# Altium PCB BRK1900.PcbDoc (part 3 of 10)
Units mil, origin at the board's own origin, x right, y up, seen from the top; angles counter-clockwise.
Board outline 8858.27 x 5905.51 mil, 10 copper layers (L1-TOP, L2-GND, L3-SIG1, L4-GND, L5-PWR, L6-PWR, L7-GND, L8-SIG2, L9-GND, L10-BOT), stack 48.824 mil thick; 507 components, 607 nets, 2498 pads, 2210 vias.
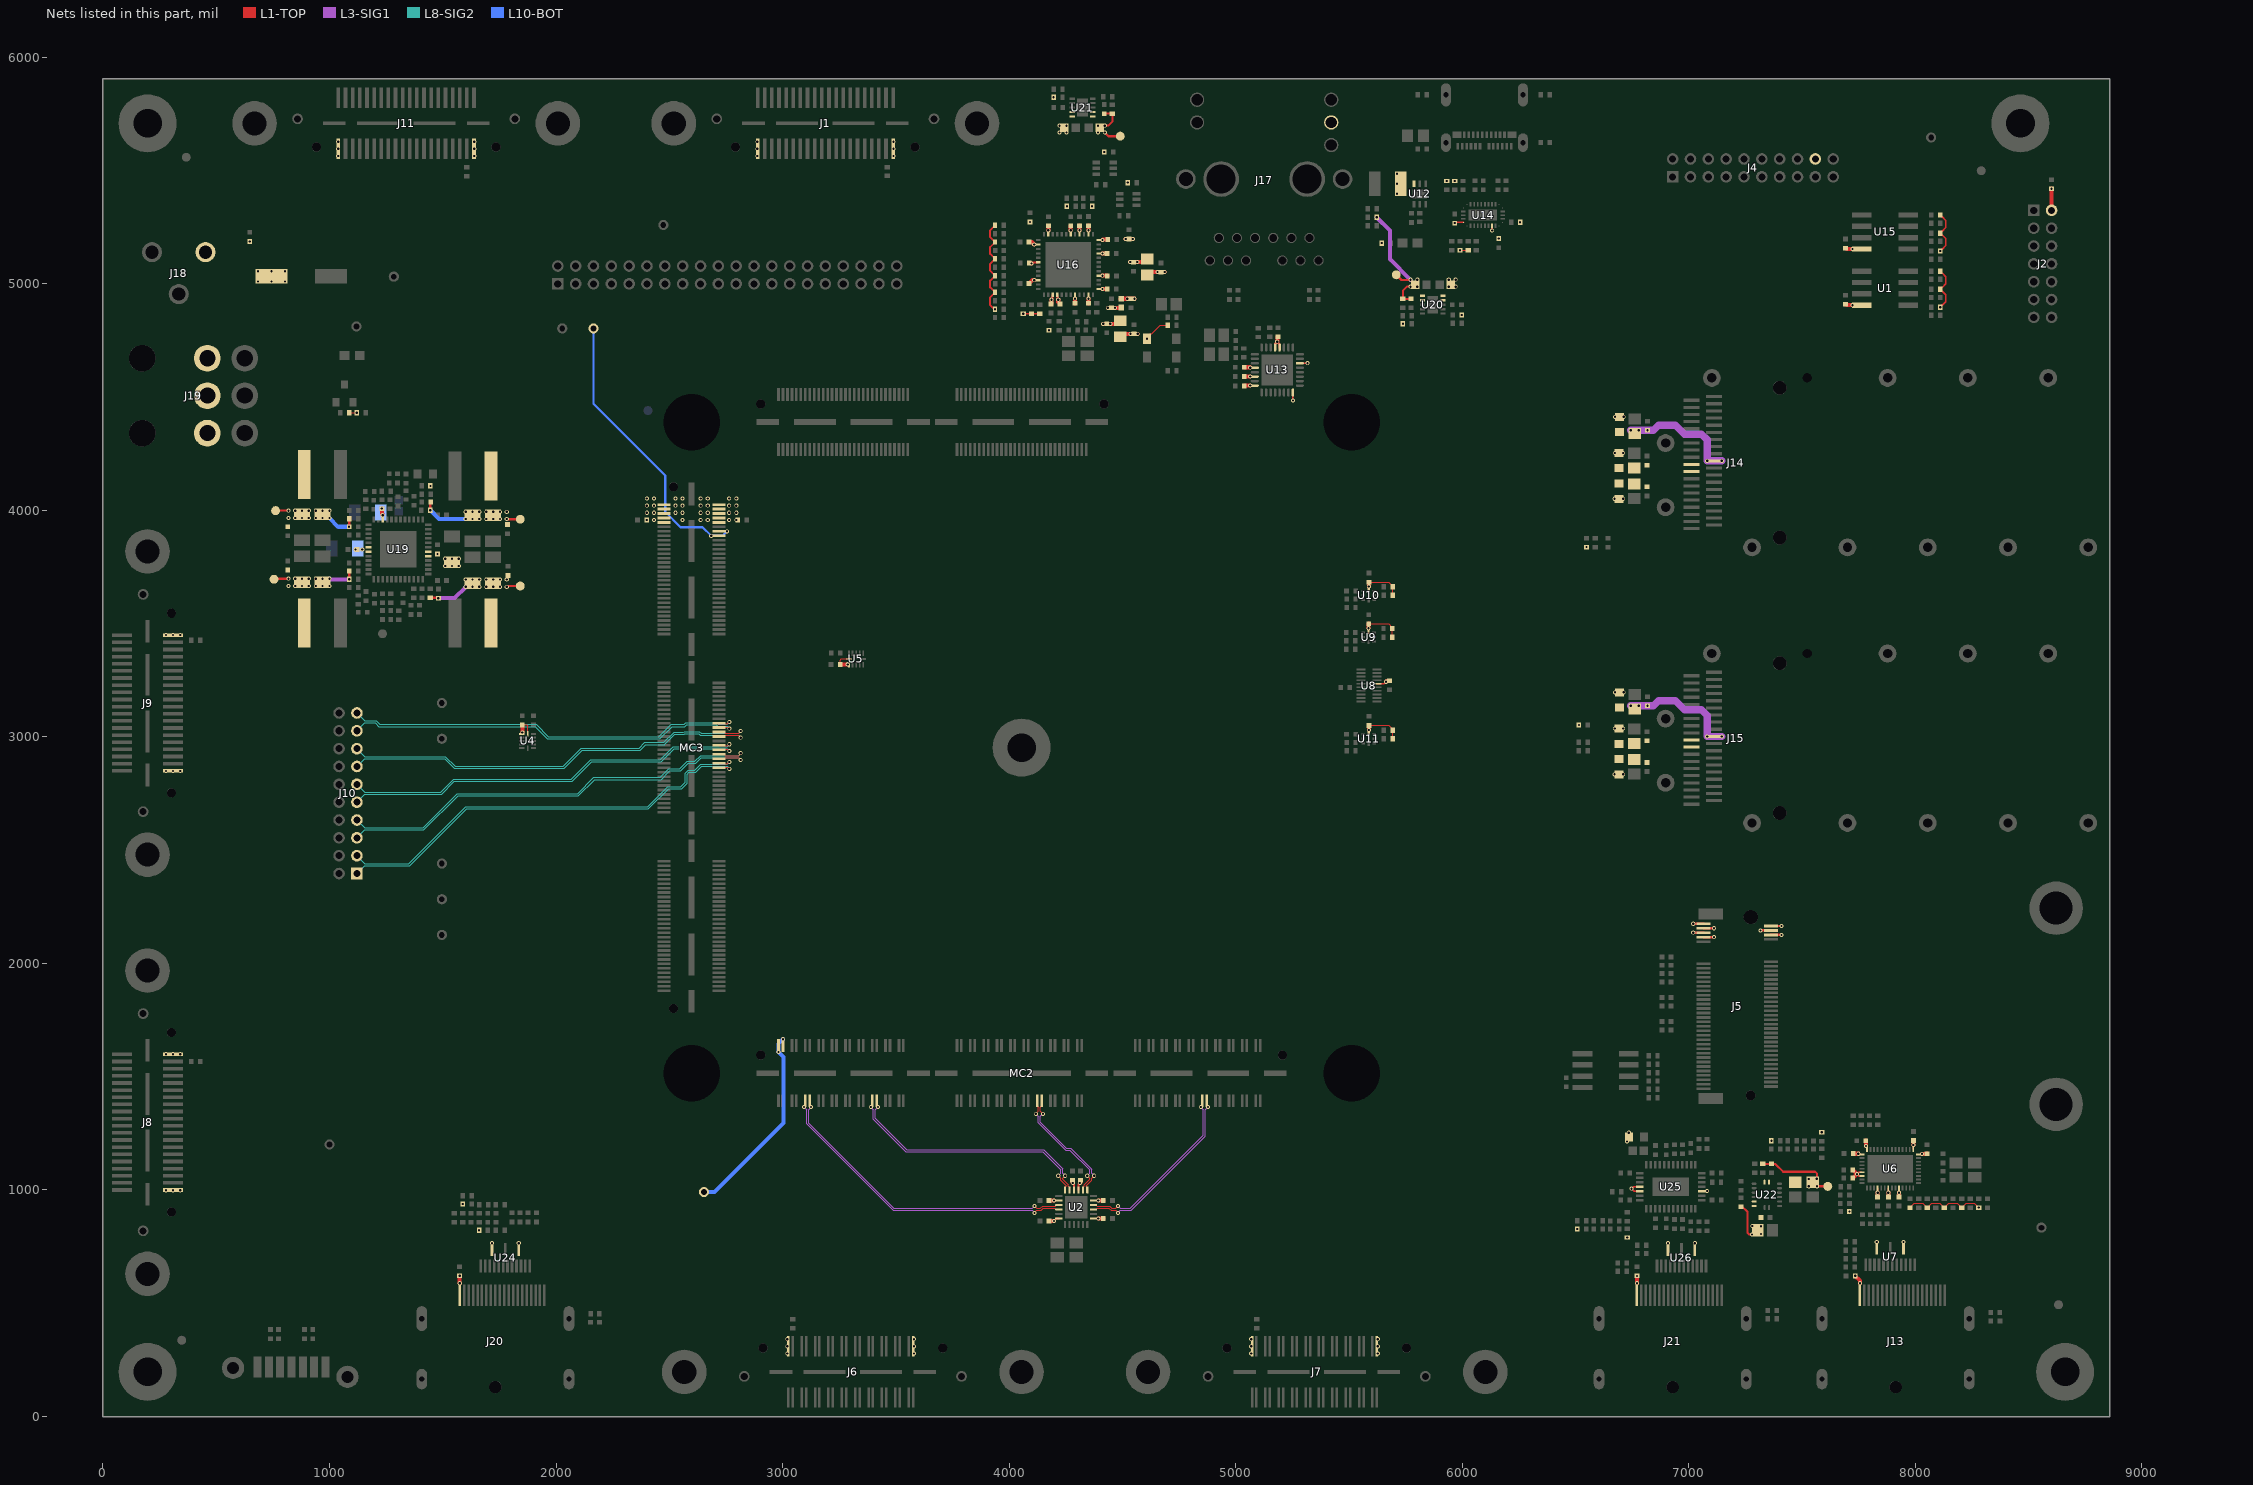
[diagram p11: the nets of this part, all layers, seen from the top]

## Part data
*1: library part OKLOGO, PartNumber=ALIGNI_IGNORE
C1 C2 C9 C70 C71 C72 C74 C82 C83 C84 C88 C89 C90 C91 C92 C93 C94 C97 C98 C99 C100 C104 C105 C106 C107 C108 C109: library part 000070, "Ceramic capacitor", Manufacturer=Kemet, ValueFloat=1E-7, x_tolerance=10
C3 C4 C5 C6 C7 C8 C10 C11 C12 C13 C14 C15 C16 C17 C18 C19 C22 C23 C40 C41 C42 C43 C44 C45 C46 C47 C48 C53 C65 C75 C76 C79 C80 C81 C118 C119 C126 C129 C139 C142 C149 C150 C174 C175 C192 C193 C194 C195 C196 C197 C198 C199 C200 C201: library part 000070, Manufacturer=Kemet, ValueFloat=1E-7, x_tolerance=10
C20 C21: library part 001073, "Ceramic capacitor", Manufacturer="Taiyo Yuden", ValueFloat=1E-7, x_tolerance=10
C24 C25 C26 C27 C28 C29 C30 C31 C32 C33 C34 C35 C36 C49 C51 C55 C56 C57 C58 C59 C60 C61 C63 C67 C68 C170 C171 C172 C173 C182 C183 C185 C187 C189 C202 C203 C204 C205 C206 C207 C208 C209 C210: library part 000070, Manufacturer=Kemet, Manufacturer_PN=C0402C104K8PACTU, ValueFloat=1E-7, x_tolerance=10
C37 C161 C163 C167 C168 C190 C211: library part 000295, Manufacturer=Kemet, ValueFloat=1E-8, x_tolerance=10
C38 C39: library part 001297, Manufacturer=Kemet, ValueFloat=1E-11, x_tolerance=5, x_voltage-rating=50
C50 C52 C54 C62 C64 C66: library part 001792, Manufacturer="Samsung Electro-Mechanics", ValueFloat=2.2E-5, x_tolerance=20
C69: library part 001258, "Ceramic Capacitor", Manufacturer="Taiyo Yuden", ValueFloat=0.00022, x_tolerance=20
C73: library part 000752, "Ceramic Capacitor", Manufacturer="Taiyo Yuden", ValueFloat=2.2E-6, x_tolerance=20
C77 C78: library part 000808, "Ceramic capacitor", Manufacturer=Kemet, ValueFloat=1.2E-11, x_tolerance=5
C85 C87 C96 C101 C103: library part 000824, "Ceramic capacitor", Manufacturer="Taiyo Yuden", ValueFloat=4.7E-6, x_tolerance=20
C86 C95 C102 C114: library part 000824, Manufacturer="Taiyo Yuden", ValueFloat=4.7E-6, x_tolerance=20
C110 C111: library part 001640, "Ceramic capacitor", Manufacturer=Kemet, ValueFloat=1.8E-11, x_tolerance=5, x_voltage-rating=50
C112: library part 000491, "Ceramic capacitor", Manufacturer="Taiyo Yuden", ValueFloat=1E-5, x_tolerance=10
C113 C158 C159 C162 C164 C191: library part 001346, Manufacturer="Taiyo Yuden", ValueFloat=1E-5, x_tolerance=20
C115: library part 001926, Manufacturer=TDK, ValueFloat=3.3E-6, x_tolerance=20
C116 C127 C140: library part 001172, "Ceramic Capacitor", Manufacturer=TDK, Tolerance (%)=20, ValueFloat=2.2E-5, Voltage=35V, x_voltage-rating=35
C117 C128 C141: library part 001073, "Ceramic capacitor", Manufacturer="Taiyo Yuden", Tolerance (%)=10, ValueFloat=1E-7, Voltage=25V
C120 C121 C130 C131 C143 C144 C151 C152: library part 001284, "Ceramic capacitor", Manufacturer="Taiyo Yuden", Tolerance (%)=10, ValueFloat=2.2E-5
C122 C133: library part 001004, Manufacturer=Kemet, Manufacturer_PN=C0402C560J5GACTU, ValueFloat=5.6E-11, x_temperature_characteristic=C0G, x_tolerance=5
C123 C136 C155: library part 000930, "Ceramic capacitor", Manufacturer=Kemet, Tolerance (%)=10, ValueFloat=4.7E-9
C124 C132 C138 C146: library part 000070, "Ceramic capacitor", Manufacturer=Kemet, Tolerance (%)=10, ValueFloat=1E-7
C125 C137 C148 C157: library part 000807, "Ceramic capacitor", Manufacturer=Kemet, Tolerance (%)=5, ValueFloat=2.2E-11
C134: library part 001532, "Polarized", Manufacturer=Panasonic, ValueFloat=0.00022, x_tolerance=20, x_voltage-rating=25
C135: library part 001073, Manufacturer="Taiyo Yuden", ValueFloat=1E-7, x_tolerance=10
C145 C153: library part 001004, "Ceramic capacitor", Manufacturer=Kemet, Tolerance (%)=5, ValueFloat=5.6E-11
C147: library part 000930, Manufacturer=Kemet, ValueFloat=4.7E-9, x_tolerance=10
C154: library part 000400, Manufacturer=Kemet, Manufacturer_PN=C0402C101J5GACTU, ValueFloat=1E-10
C156 C166: library part 000962, "Ceramic capacitor", Manufacturer=Murata, Tolerance (%)=3.125, ValueFloat=5E-12
C160: library part 000491, Manufacturer="Taiyo Yuden", ValueFloat=1E-5, x_tolerance=10
C165: library part 000963, "Ceramic capacitor", Manufacturer=Kemet, Tolerance (%)=10, ValueFloat=6.8E-10
C169 C176: library part 000961, "Ceramic capacitor", Manufacturer=Kemet, Tolerance (%)=20, ValueFloat=2.2E-5
C177: library part 000480, "Ceramic capacitor", Manufacturer="Taiyo Yuden", Tolerance (%)=10, ValueFloat=1E-6
D1: library part 001432, "LED", Manufacturer=Dialight, Manufacturer_PN=598-8010-107F
D2 D3: library part 001302, "Default Diode", Manufacturer="Micro Commercial Co", Manufacturer_PN=1N4148W-TP
D4: library part 001433, "LED", Manufacturer=Dialight, Manufacturer_PN=598-8070-107F
FB1: library part 000783, "Ferrite Chip", Manufacturer=Murata, ValueFloat=220
FB2: library part 000584, "Ferrite Bead", Manufacturer=Steward, ValueFloat=1000
FB3 FB4: library part 000100, "Ferrite bead", Manufacturer=Steward, ValueFloat=600
FID1 FID2 FID3 FID4 FID5 FID6 FID7 FID8: "PCB fiducial", PartNumber=ALIGNI_IGNORE
J1 J8 J9 J11: library part 001604, "0.8mm hi-speed, high-density header (male)", Manufacturer=Samtec
J2: library part 000541, "2mm header, shrouded", Manufacturer=Molex
J3: library part 000583, Manufacturer=Molex
J4 J10: library part 001338, Manufacturer=Molex
J5: library part 001722, "M.2 (NGFF) edge card connector, 4.2 mm height, M keying", Manufacturer=Amphenol
J6 J7: library part 000694, "0.5mm hi-speed, high-density socket (male)", Manufacturer=Samtec
J12: library part 000988, "SATA 7-pin receptacle", Manufacturer=Molex
J13 J20 J21: library part 001943, Manufacturer=Molex
J14 J15: library part 001782, "QSFP28 38-POS Receptacle", Manufacturer=Amphenol
J16: library part 001907, Manufacturer=Molex
J17: library part 001517, "RJ-45", Manufacturer="Bel Fuse, Inc."
J18: library part 000356, Manufacturer="CUI Inc."
J19: library part 001950, Manufacturer=Molex
JSO1 JSO2 JSO3 JSO4: library part 001879, "Jack screw standoff, 5mm board stack height", Manufacturer=Samtec, Manufacturer_PN=JSO-0515-01
L1 L2 L3 L4: library part 001543, "Power inductor, 2.2uH, 7A, 12.7mOhm", Manufacturer=Coilcraft, Tolerance (%)=20, ValueFloat=2.2E-6
MC1: library part 000855, "0.5mm Double Row High Speed Socket Assembly", Manufacturer=Samtec
MC2: library part 001769, Manufacturer=Samtec
MC3: library part 000876, "0.5mm Double Row High Speed Socket Assembly", Manufacturer=Samtec
MH1 MH2 MH3 MH4 MH5 MH6 MH7 MH8 MH9 MH10 MH11 MH12 MH13 MH14 MH15 MH16 MH17: "Mounting hole", PartNumber=ALIGNI_IGNORE
Q1: library part 001237, "N-Channel MOSFET", Manufacturer="Fairchild Semiconductor", Manufacturer_PN=FDN337N, PackageDocument=1995/1996
QSFP1 QSFP2: library part 001781, "QSFP28 Single Cage", Manufacturer=Amphenol
R1: library part 001551, Manufacturer=Vishay, ValueFloat=34000, x_tolerance=1
R2 R3 R4 R5 R6 R7 R8 R9 R10 R11 R12 R13 R68 R74 R80 R81 R83 R84 R85 R86 R87 R88 R89 R104 R110 R111 R112 R119: library part 001521, "Thick-film resistor", Manufacturer=Vishay, ValueFloat=10000, x_tolerance=1
R14: library part 000934, Manufacturer=Vishay, ValueFloat=24900, x_tolerance=1
R15: library part 001783, Manufacturer=Vishay, ValueFloat=18700, x_tolerance=1
R16: library part 001549, "Thick-film resistor", Manufacturer=Vishay, ValueFloat=210000, x_tolerance=1
R17: library part 001550, "Thick-film resistor", Manufacturer=Vishay, ValueFloat=84500, x_tolerance=1
R18: library part 001035, Manufacturer=Vishay, ValueFloat=49900, x_tolerance=1
R19 R20 R21 R22 R67 R70 R73 R77 R78 R79 R117 R145 R146 R150 R151 R165: library part 000755, "Thick-film resistor", Manufacturer=Vishay, ValueFloat=0, x_tolerance=1
R23 R24 R25 R26 R27 R28 R29 R155 R156 R157 R162 R163 R164: library part 001850, Manufacturer=Vishay, ValueFloat=1000000, x_tolerance=5
R30 R31 R32 R33 R34 R36 R37 R38 R39 R40 R131 R139 R140: library part 001521, Manufacturer=Vishay, ValueFloat=10000, x_tolerance=1
R35 R154 R159 R166 R167 R171 R173: library part 001070, Manufacturer=Vishay, ValueFloat=100000, x_tolerance=1
R41 R42 R43 R52 R53 R54 R136 R160: library part 000411, Manufacturer=Vishay, ValueFloat=0
R44 R45 R48 R49 R57 R58 R63 R64: library part 000754, Manufacturer=Vishay, ValueFloat=4700, x_tolerance=5
R46 R47 R59 R60: library part 000755, Manufacturer=Vishay, ValueFloat=0, x_tolerance=1
R50 R51 R55 R56 R61 R62: library part 001126, Manufacturer=Vishay, Manufacturer_PN=CRCW04023K01FKED, ValueFloat=3010, x_tolerance=1
R65: library part 001162, Manufacturer=Vishay, ValueFloat=2000, x_tolerance=1
R66: library part 001121, Manufacturer=Vishay, ValueFloat=15000, x_tolerance=1
R69 R115 R116: library part 000797, "Thick-film resistor", Manufacturer=Vishay, ValueFloat=1000, x_tolerance=1
R71: library part 001945, Manufacturer=Vishay, ValueFloat=499000, x_tolerance=1
R72: library part 001853, Manufacturer=Vishay, ValueFloat=887000, x_tolerance=1
R75 R113: library part 000800, "Thick-film resistor", Manufacturer=Vishay, ValueFloat=1000000, x_tolerance=5
R76: library part 001266, "Thick-film resistor", Manufacturer=Vishay, ValueFloat=8060, x_tolerance=1
R82: library part 001549, Manufacturer=Vishay, ValueFloat=210000, x_tolerance=1
R90 R91 R92 R93 R94 R95 R98 R99 R100 R101 R102 R103 R108 R114: library part 001008, "Thick-film resistor", Manufacturer=Vishay, ValueFloat=4750, x_tolerance=1
R96 R97: library part 000760, "Thick-film resistor", Manufacturer=Vishay, ValueFloat=240, x_tolerance=1
R105 R106 R107 R118: library part 001388, "Thick-film resistor", Manufacturer=Vishay, ValueFloat=2490, x_tolerance=1
R109: library part 001530, "Thick-film resistor", Manufacturer=Vishay, ValueFloat=12100, x_tolerance=1
R120 R121 R148: library part 001521, "Thick-film resistor", Manufacturer=Vishay, Tolerance (%)=1, ValueFloat=10000
R122 R125: library part 001091, Manufacturer=Vishay, Manufacturer_PN=CRCW040231K6FKED, ValueFloat=31600, x_tolerance=1
R123 R126 R130 R135: library part 001521, Manufacturer=Vishay, Manufacturer_PN=CRCW040210K0FKED, ValueFloat=10000, x_tolerance=1
R124 R127 R129 R133: library part 001121, "Thick-film resistor", Manufacturer=Vishay, Tolerance (%)=1, ValueFloat=15000
R128 R132: library part 001157, Manufacturer=Vishay, ValueFloat=52300, x_tolerance=1
R134: library part 001618, "Thick-film resistor", Manufacturer=Vishay, Tolerance (%)=1, ValueFloat=374000
R137 R149: library part 000759, Manufacturer=Vishay, ValueFloat=10000, x_tolerance=5
R138: library part 001162, "Thick-film resistor", Manufacturer=Vishay, Tolerance (%)=1, ValueFloat=2000
R141 R147: library part 000965, "Thick-film resistor", Manufacturer=Vishay, Tolerance (%)=1, ValueFloat=237000
R142: library part 001266, Manufacturer=Vishay, ValueFloat=8060, x_tolerance=1
R143: library part 001282, Manufacturer=Vishay, ValueFloat=20000, x_tolerance=1
R144: library part 000969, "Thick-film resistor", Manufacturer=Vishay, Tolerance (%)=1, ValueFloat=10
R153 R158 R170 R172 R178 R179: library part 001715, Manufacturer=Vishay, ValueFloat=49.9, x_tolerance=1
R161: library part 002008, Manufacturer=Vishay, ValueFloat=1200, x_tolerance=1
R168 R174 R176: library part 001388, Manufacturer=Vishay, ValueFloat=2490, x_tolerance=1
R169 R175 R177: library part 002012, Manufacturer=Vishay, ValueFloat=1500, x_tolerance=1
R180 R181 R182: library part 000969, Manufacturer=Vishay, ValueFloat=10, x_tolerance=1
SO1 SO2: library part 001726, "Mounting hole", Manufacturer=Wurth, Manufacturer_PN=9774025151R
TP1 TP2 TP3 TP4 TP5 TP6 TP7 TP8 TP9 TP10 TP11 TP12 TP13 TP14: library part TP-PTH-25/45, "Test point, plated through-hole, 25/45mil", PartNumber=ALIGNI_IGNORE
TP15 TP16 TP17 TP18 TP20 TP21 TP22: library part TESTPOINT-SMD40, "Test point, surface-mount, 40mil"
TP19: "Test point, surface-mount, 40mil"
U1 U3: library part 000842, "EEPROM", Manufacturer=Microchip
U2: library part 001741, Manufacturer="Silicon Labs"
U4 U5: library part 001161, Manufacturer="Texas Instruments"
U6: library part 002001, Manufacturer="Kinetic Technologies"
U7 U24 U26: library part 001946, Manufacturer="Texas Instruments"
U8: library part 001324, Manufacturer="Texas Instruments"
U9 U10 U11: library part 001559, Manufacturer="ON Semiconductor"
U12: library part 001278, "Adjustable current-limited power switch", Manufacturer="Texas Instruments"
U13: library part 001262, "Hi-Speed USB PHY with ULPI interface", Manufacturer=Microchip
U14: library part 001944, Manufacturer="Texas Instruments"
U15: library part 001296, "2 kb I2C EEPROM, 400 kHz", Manufacturer=Microchip
U16: library part 001518, "Gigabit ethernet transceiver, RGMII", Manufacturer=Micrel
U17 U18: library part 000600, "Small Signal MOSFET Dual N-Channel", Manufacturer="Fairchild Semiconductor", PackageDocument=1995/1996
U19: library part 001511, Manufacturer="Texas Instruments"
U20 U21: library part 001932, Manufacturer="Texas Instruments"
U22: library part 000960, Manufacturer=Altera
U25: library part 002007, Manufacturer="Texas Instruments"
Y1: library part 001742, Manufacturer=Epson
Y2: library part 001531, Manufacturer=Abracon
Y3: library part 000770, "Crystal", Manufacturer="MMD Monitor / Quartztek"
Y4: library part 001531, "Crystal", Manufacturer=Abracon

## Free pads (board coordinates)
  round 18 hole 10 mask+2: ViaNoConnect1(1086.5,3927.64) ViaNoConnect1(1086.82,3695.64) ViaNoConnect1(1444.95,4000.64) ViaNoConnect1(1480.58,3612.56)

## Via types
v1: diameter 18, hole 10, L1-TOP to L10-BOT, tented both sides, 2210 vias

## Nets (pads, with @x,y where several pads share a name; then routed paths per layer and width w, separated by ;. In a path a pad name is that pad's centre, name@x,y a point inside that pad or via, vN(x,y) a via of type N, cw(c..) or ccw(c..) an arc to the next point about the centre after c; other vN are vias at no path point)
+1.2V_DP: C40.2 C41.2 C42.2 C43.2 C44.2 C45.2 C46.2 C166.2 C169.2 C176.2 R141.2 TP20.1 U6.9 U6.10 U6.23 U6.24 U6.36 U6.39 U6.42 U22.7 U22.8 | length 582.5
  L1-TOP w7.5: v1(7834.02,988.28) U6.36@7834.02,1008 ; v1(7881.26,988.28) U6.39@7881.26,1008 ; v1(7928.5,988.28) U6.42@7928.5,1008 ; U6.10@7991.5,1179.26 v1(7991.5,1198.98)
  L1-TOP w8: TP20.1@7612.25,1014.25 TP20.1@7614,1016
  L1-TOP w9: R141.2@7327,1114.59 7365,1114.59 7382.89,1114.59 7417,1080.48 7558.18,1080.48 7565.45,1073.21 v1(7565.45,1049.29)
  L1-TOP w10: C169.2@7547,1033.96 7564.96,1016 TP20.1@7614,1016
  L1-TOP w18: C43.2@7725.85,1160.26 7726.49,1159.62 7726.7,1159.84 v1(7748.64,1159.84) ; C46.2@7781.85,1217.26 7782.9,1216.21 v1(7782.9,1194.02) ; C41.2@7832.77,969.34 7834.02,970.58 v1(7834.02,988.28) ; v1(7881.26,988.28) 7881.26,970.85 C40.2@7882.77,969.34 ; v1(7928.5,988.28) 7928.5,969.61 C42.2@7928.77,969.34 ; v1(7991.5,1198.98) 7991.5,1217.98 C44.2@7991.77,1218.26 ; v1(8030.08,1159.65) 8052.25,1159.65 C45.2@8052.77,1160.18
  other v1: 7530.21,1015.98 7566,1015.98 7530,1049
+1.2V_ETH: C87.1 C88.2 C89.2 C90.2 C91.2 C92.2 C93.2 C95.2 C102.2 C163.2 C164.2 FB3.1 FB4.1 R140.2 TP22.1 U16.14 U16.18 U16.23 U16.26 U16.30 U16.39 U21.1 U21.2 | length 519.2
  L1-TOP w9: C91.2@4096.58,5092.14 4099.57,5095.12 U16.30@4128.04,5095.12 ; 4192.58,4938.1 4192.58,4951 U16.39@4193,4951.42 ; C163.2@4418,5752.38 R140.2@4454,5752.38 ; v1@4421.53,5698.46 v1(4422.53,5698.46) 4438,5698.46 4456,5716.46 R140.2@4456,5751.77
  L1-TOP w10: v1@4421.53,5668.93 v1(4422.53,5667.93) 4438.46,5652 TP22.1@4491,5652
  L1-TOP w18: C93.2@4088.14,5184.14 4100.77,5184.14 v1(4111.04,5173.86) ; C91.2@4089.14,5092.14 4096.58,5092.14 v1(4098.48,5090.24) ; C88.2@4173.06,5256.06 4173.32,5255.8 v1(4173.32,5236.14) ; C92.2@4185.06,4911.22 4185.65,4911.22 4186.89,4912.45 4186.89,4929.97 v1(4187.06,4930.14) ; v1(4271.74,5236.14) 4271.74,5255.75 C90.2@4272.06,5256.06 ; v1(4350.49,5236.14) 4350.49,5256.57 C89.2@4351.06,5257.14 ; FB3.1@4491,4766.13 4504.35,4779.49 v1(4536.25,4779.49) C95.2@4552,4779.49 v1(4567.75,4779.49) ; FB4.1@4610.02,5038.64 4623.37,5051.99 v1(4655.27,5051.99) C102.2@4671.02,5051.99 v1(4686.76,5051.99)
  other v1: 4092,5272.92 4392,5667.93 4392,5698.46
+1.8V: MC2.1 MC2.3 TP1.1 | length 864.5
  L10-BOT w18: TP1.1@2653,991 2700,991 3004,1295 3004,1587.68 v1(2982.28,1609.4) 2982.28,1645.72 v1(3001.97,1665.4)
+1.8V_AUX: C1.2 C47.2 C48.2 C71.2 C72.2 C74.2 C98.2 C99.2 C100.2 C101.1 C161.2 C162.2 D2.2 J2.2 J4.18 J5.69 J5.70 J5.71 R30.2 R31.2 R32.2 R33.2 R34.2 R68.2 R90.2 R91.2 R92.2 R93.2 R94.2 R95.2 R105.2 R106.2 R107.2 R108.2 R110.2 R111.2 R118.2 R139.2 TP21.1 U6.29 U6.30 U13.8 U13.14 U13.28 U13.30 U13.32 U16.16 U16.34 U16.40 U20.1 U20.2 | length 2167.8
  L1-TOP w5: v1(4608.72,4757.57) 4608.72,4763.43 4624.13,4778.84 4629.98,4778.84 4667.72,4816.57 R118.2@4699.6,4816.57 ; R30.2@7976.77,922.57 7996.46,942.26 8033.09,942.26 R31.2@8052.77,922.57 8072.46,942.26 8109.09,942.26 R32.2@8128.77,922.57 8148.46,942.26 8185.09,942.26 R33.2@8204.77,922.57 8224.46,942.26 8261.09,942.26 v1(8280.77,922.57)
  L1-TOP w7: U13.8@5252.84,4520.65 5252.84,4485.43 v1(5253.41,4484.87) ; U13.14@5283.35,4649.58 5317.13,4649.58 v1(5317.41,4649.87)
  L1-TOP w7.5: U6.30@7764.13,1062.13 7750.98,1062.13 v1(7743.18,1069.93) 7751.12,1077.88 U6.29@7764.13,1077.88
  L1-TOP w8: v1(3937.8,4888.42) 3933.58,4888.42 3916,4906 3916,4940.62 R90.2@3937.8,4962.42 3916,4984.22 3916,5014.62 R95.2@3937.8,5036.42 3916,5058.22 3916,5088.62 R94.2@3937.8,5110.42 3916,5132.22 3916,5162.62 R93.2@3937.8,5184.42 3916,5206.22 3916,5236.62 R92.2@3937.8,5258.42 ; v1(4062,4868.31) R106.2@4099,4868.31 R107.2@4136,4868.31
  L1-TOP w9: U16.40@4212.69,4951.42 4213.11,4951 v1@4213.11,4936.52 ; R139.2@5737.94,4934.46 5737.94,4969.77 5755.94,4987.77 v1@5772.41,4987.77 ; R139.2@5739.94,4933.85 C161.2@5775.94,4933.85
  L1-TOP w10: TP21.1@5709,5040 5731.7,5017.3 v1@5772.41,5017.3
  L1-TOP w11: v1(7019.94,2135.83) J5.71@7065.94,2135.83 ; J5.69@7065.94,2116.14 v1(7111.94,2116.14) ; J5.70@7363.19,2125.98 v1(7409.19,2125.98)
  L1-TOP w18: C99.2@4088.14,5001.14 4103.38,5016.38 v1(4111.04,5016.38) ; v1(4217.06,4930.14) 4217.06,4919.22 4223.23,4913.05 4223.23,4912.45 4224.47,4911.22 C100.2@4225.06,4911.22 ; v1(4311.11,5236.14) C98.2@4311.11,5256.57 ; v1(4514.65,5198.31) v1(4546.14,5198.31) C101.1@4530,5198.31 ; C74.2@5038.49,4549.87 C74.2@5038.49,4549.87 5039.72,4551.16 v1(5064.54,4551.16) ; C72.2@5038.49,4590.87 5038.83,4590.53 v1(5064.54,4590.53) ; C71.2@5038.49,4631.87 5062.57,4631.87 v1(5064.54,4629.9) ; C48.2@7724.85,1052.26 7725.5,1052.26 v1(7743.18,1069.93) C47.2@7724.85,1088.26 ; J2.2@8602,5324.48 v1(8602,5419.92)
  L3-SIG1 w18: v1(5622.69,5294) 5681,5235.68 5681,5108.71 v1@5772.41,5017.3
  other v1: 4176,4795.31 5771.41,4987.77 5801.94,4987.77 5771.41,5018.3 5801.94,5018.3 4255.37,5342.14 4366.43,5342.14
+3.3V: MC3.166 MC3.168 TP3.1 | length 1265.5
  L10-BOT w10: TP3.1@2165.35,4803.15 2165.35,4470.65 2482.24,4153.76 2482.24,3993.76 2550,3926 2646.87,3926 v1(2685.08,3887.8) 2735.39,3887.8 v1(2755.08,3907.48)
+3.3V_AUX: C2.2 C3.2 C4.2 C5.2 C6.2 C7.2 C8.2 C18.2 C22.2 C29.2 C73.2 C75.2 C86.2 C94.2 C129.2 C130.2 C131.2 C133.2 C158.2 C159.2 C160.2 C165.2 C183.2 C204.2 FB2.2 J1.40 J5.72 J5.73 J5.74 J5.75 J6.40 J7.40 J8.40 J9.40 J11.40 J13.20 J17.16 J20.20 J21.20 L2.2 pad.ViaNoConnect1@1444.95,4000.64 R2.2 R3.2 R4.2 R23.2 R24.2 R65.2 R80.2 R82.2 R84.2 R85.2 R86.2 R104.2 R112.2 R125.2 R137.2 R138.2 R144.2 R145.1 R146.1 R148.2 R149.2 R160.1 R167.2 R168.2 R173.2 R174.2 R176.2 TP16.1 U1.8 U2.7 U2.11 U2.15 U2.16 U2.20 U2.24 U4.1 U4.12 U5.1 U5.12 U7.13 U7.15 U13.20 U13.21 U14.8 U15.8 U20.9 U20.10 U21.9 U21.10 U22.13 U22.14 U24.13 U24.15 U25.16 U25.17 U25.34 U26.13 U26.15 | length 1931.8
  L1-TOP w5: R148.2@1087.69,4431 v1(1120.32,4431) ; C18.2@1851,3052.92 1871.08,3052.92 1875,3049 U4.12@1875,3013.5 ; C22.2@3254.25,3320.17 3254.25,3338.25 3260,3344 U5.12@3293.5,3344
  L1-TOP w6: U25.17@6784.8,995.2 6758.54,995.2 v1(6747.72,1006.01) 6756.59,1014.88 U25.16@6784.8,1014.88
  L1-TOP w7: U14.8@6131.75,5256 6131.75,5236.75 v1(6132.55,5235.95) ; v1(8110.69,4897) 8110.69,4898.97 8117.03,4905.31 8119,4905.31 8134.97,4921.28 8134.97,4951.72 8119,4967.69 8117.03,4967.69 8110.69,4974.03 R3.2@8110.69,4976 8110.69,4977.97 8117.03,4984.31 8119,4984.31 8134.97,5000.28 8134.97,5031.72 8119,5047.69 8117.03,5047.69 8110.69,5054.03 R4.2@8110.69,5056 ; v1(8110.69,5145) 8110.69,5146.97 8117.03,5153.31 8119,5153.31 8134.97,5169.28 8134.97,5199.72 8119,5215.69 8117.03,5215.69 8110.69,5222.03 R85.2@8110.69,5224 8110.69,5225.97 8117.03,5232.31 8119,5232.31 8134.97,5248.28 8134.97,5279.72 8119,5295.69 8117.03,5295.69 8110.69,5302.03 R86.2@8110.69,5304
  L1-TOP w9: v1(4198.46,863.57) 4209.46,874.57 U2.24@4219.46,874.57 ; v1(4281.22,1030.58) 4286.39,1025.42 U2.16@4286.39,1000.56 ; U2.15@4306.07,1000.56 4306.07,1024.4 v1(4312.26,1030.58) ; R144.2@7235,927.76 7260,902.76 7260,810.12 7266.63,803.48 v1(7279,803.48)
  L1-TOP w10: v1(1782.58,3961.64) 1783.22,3961 TP16.1@1842,3961 ; U13.21@5174.1,4719.46 5174.3,4719.66 5174.3,4734.69 5183.41,4743.8 5193.59,4733.62 5193.59,4719.66 U13.20@5193.79,4719.46
  L1-TOP w11: R125.2@1444.95,4000.64 1444.95,4034.93 C133.2@1446.66,4036.64 ; v1(7019.94,2175.2) J5.75@7065.94,2175.2 ; J5.73@7065.94,2155.51 v1(7111.94,2155.51) ; v1(7317.19,2145.67) J5.72@7363.19,2145.67 ; J5.74@7363.19,2165.35 v1(7409.19,2165.35)
  L1-TOP w18: v1(1574.53,620.92) 1574.53,588.82 v1(1575.01,588.34) ; C18.2@1851,3052.92 1851.17,3052.75 v1(1851.17,3019.32) ; C22.2@3254.25,3320.17 v1(3287.68,3320.17) ; C7.2@4176.31,863.79 4176.52,863.57 v1(4198.46,863.57) ; C4.2@4176.31,953.79 4197.98,953.79 v1(4198.46,953.31) ; C6.2@4279.23,1043.71 4279.23,1032.58 v1(4281.22,1030.58) ; v1(4312.26,1030.58) 4315.23,1033.55 C8.2@4315.23,1043.71 ; v1(4394,874.57) 4415.36,874.57 C3.2@4416.15,873.79 ; v1(4394,953.31) 4415.68,953.31 C5.2@4416.15,953.79 ; FB2.2@4492.61,4933.98 FB2.2@4493,4934.37 ; FB2.2@4497,4934.37 v1(4521.86,4934.37) C86.2@4537.61,4934.37 v1(4553.35,4934.37) ; v1(5183.41,4744.87) 5184.58,4746.04 5184.58,4764.55 5185.82,4765.79 C73.2@5186.41,4765.79 ; C204.2@6771.53,620.92 v1(6771.86,620.59) v1(6771.86,588.34) ; C2.2@7693,4909.92 7693.59,4909.92 7697.51,4906 v1(7722.64,4906) U1.8@7764.64,4906 ; C94.2@7693,5157.92 7693.59,5157.92 7697.51,5154 v1(7722.64,5154) U15.8@7764.64,5154 ; v1(7734.61,621) 7756.11,599.49 v1(7756.11,588.34)
  L10-BOT w18: pad.ViaNoConnect1@1444.95,4000.64 1483.95,3961.64 v1(1601.58,3961.64)
  other v1: 3580.33,278.35 5627.57,278.35 3580.33,309.84 5627.57,309.84 3580.33,341.34 5627.57,341.34 1717.2,765.39 1835.31,765.39 6908.93,765.24 7027.04,765.24 7830.12,770.39 7948.23,770.39 6729,790.32 7319.24,805.27 1660.16,822 6508.31,828 7318.97,839.39 7281.01,840.62 7709.69,905 1588.84,938 7081.43,995.2 278.15,998.81 309.65,998.81 341.15,998.81 6727.2,1214.06 7365.31,1217 6735.9,1253.13 7587,1254.68 278.15,2849.21 309.65,2849.21 341.15,2849.21 1631.58,3961.64 1661.58,3961.64 1692.58,3961.64 1722.58,3961.64 1752.58,3961.64 1601.58,3993.81 1631.58,3993.81 1661.58,3993.81 1692.58,3993.81 1722.58,3993.81 1752.58,3993.81 1782.58,3993.81 1445.69,4108 5738.57,4823.77 5997.62,4862.77 5940.94,4987.77 5971.46,4987.77 5940.94,5018.3 5971.46,5018.3 5645.31,5180 6161.35,5200.08 6255.78,5272.32 4523.31,5447 5931.41,5454.01 1038.18,5564.37 2888.58,5564.37 4420.31,5582 1038.18,5595.86 2888.58,5595.86 1038.18,5627.36 2888.58,5627.36 4222.47,5667.93 4253,5667.93 4222.47,5698.46 4253,5698.46 4196.31,5823.46
+3.3V_QSFP: C56.2 C58.2 C60.2 C68.2 C119.2 C120.2 C121.2 C122.2 L1.2 pad.ViaNoConnect1@1480.58,3612.56 R41.1 R42.1 R43.2 R44.2 R45.2 R48.2 R49.2 R52.1 R53.1 R54.2 R57.2 R58.2 R63.2 R64.2 R122.2 TP15.1 U8.16 U9.8 U10.8 U11.8 | length 821.6
  L1-TOP w5: C58.2@5587.46,3499.57 5675.54,3499.57 5692.14,3482.96 R58.2@5692.14,3478.65 R45.2@5692.14,3440.65 ; C68.2@5588.46,3050.57 5676.54,3050.57 5693.14,3033.96 R63.2@5693.14,3029.65 R64.2@5693.14,2991.65 ; C60.2@5588.46,3683.57 5676.54,3683.57 5693.14,3666.96 R48.2@5693.14,3662.65 R49.2@5693.14,3624.65
  L1-TOP w7.5: U8.16@5623.43,3234.87 5654.74,3234.87 v1(5663.37,3243.5)
  L1-TOP w10: v1(1782.58,3662.46) 1786.12,3666 TP15.1@1842,3666
  L1-TOP w11: R122.2@1444.58,3613.95 1479.19,3613.95 C122.2@1480.58,3612.56
  L1-TOP w18: v1(5587,3479.64) 5587,3499.11 C58.2@5587.46,3499.57 ; v1(5588,3030.64) 5588,3050.11 C68.2@5588.46,3050.57 ; v1(5588,3663.64) 5588,3683.11 C60.2@5588.46,3683.57 ; v1(5663.37,3243.5) 5667.61,3247.74 C56.2@5678.63,3247.74
  L3-SIG1 w18: pad.ViaNoConnect1@1480.58,3612.56 1551.68,3612.56 v1(1601.58,3662.46)
  other v1: 6672.79,2834.78 6710.79,2834.78 6673.87,3036.71 6710.79,3036.71 6515.31,3052.7 6675,3196.65 6713,3196.65 1631.58,3662.46 1661.58,3662.46 1692.58,3662.46 1722.58,3662.46 1752.58,3662.46 1601.58,3694.64 1631.58,3694.64 1661.58,3694.64 1692.58,3694.64 1722.58,3694.64 1752.58,3694.64 1782.58,3694.64 6549,3838.02 6672.8,4051.25 6710.8,4051.25 6673.88,4253.18 6710.8,4253.18 6675.01,4413.12 6713.01,4413.12
+3.3V_QSFP_VCC1: C53.2 C54.2 J14.30 R43.1
+3.3V_QSFP_VCC2: C65.2 C66.2 J15.30 R54.1
+3.3V_QSFP_VCCRX1: C51.2 C52.2 J14.10 R42.2 | length 531
  L3-SIG1 w32: v1(6744.01,4353.65) v1(6780.01,4353.65) 6780.09,4353.57 v1(6818.01,4353.57) 6844.87,4353.57 6867,4375.7 6941.87,4375.7 6981.04,4336.53 7056.17,4336.53 7081.38,4311.32 v1(7081.38,4218.61) v1(7146.43,4218.61)
+3.3V_QSFP_VCCRX2: C63.2 C64.2 J15.10 R53.2 | length 531
  L3-SIG1 w32: v1(6744,3137.18) v1(6780,3137.18) 6780.08,3137.1 v1(6818,3137.1) 6844.87,3137.1 6866.99,3159.23 6941.87,3159.23 6981.03,3120.06 7056.16,3120.06 7081.37,3094.85 v1(7081.37,3002.13) v1(7146.43,3002.13)
+3.3V_QSFP_VCCTX1: C49.2 C50.2 J14.29 R41.2
+3.3V_QSFP_VCCTX2: C61.2 C62.2 J15.29 R52.2
+5V_AUX: C69.2 C76.2 C142.2 C143.2 C144.2 C145.2 L3.2 pad.ViaNoConnect1@1086.5,3927.64 R71.2 R74.2 R81.2 R128.2 TP17.1 U12.6 U14.30 | length 271.7
  L1-TOP w5: v1(5990.41,5148.64) R74.2@6026.41,5148.64
  L1-TOP w7.5: v1(5967.41,5268.24) 5970.91,5271.75 U14.30@6005.76,5271.75
  L1-TOP w10: TP17.1@762,3999 818.39,3999 v1(818.58,3998.81)
  L1-TOP w11: C145.2@1086.5,3927.64 1086.5,3963.24 R128.2@1086.9,3963.64
  L10-BOT w18: v1(999.58,3966.64) 1038.58,3927.64 pad.ViaNoConnect1@1086.5,3927.64
  other v1: 818.58,3966.64 848.58,3966.64 878.58,3966.64 908.58,3966.64 939.58,3966.64 969.58,3966.64 848.58,3998.81 878.58,3998.81 908.58,3998.81 939.58,3998.81 969.58,3998.81 999.58,3998.81 5712.24,5397.96 5712.24,5441.96 5967.41,5454.01 5712.24,5485.96
+5V_SZG: C150.2 C151.2 C152.2 C153.2 J1.2 J6.2 J7.2 J8.2 J9.2 J11.2 L4.2 pad.ViaNoConnect1@1086.82,3695.64 R132.2 TP18.1 | length 189.2
  L1-TOP w10: TP18.1@755,3696 757.64,3698.64 v1(818.58,3698.64)
  L1-TOP w11: pad.ViaNoConnect1@1086.82,3695.64 R132.2@1086.9,3695.64 C153.2@1086.9,3731.64
  L3-SIG1 w18: v1(999.58,3698.53) 1002.47,3695.64 pad.ViaNoConnect1@1086.82,3695.64
  other v1: 3021.15,278.35 5068.39,278.35 3021.15,309.84 5068.39,309.84 3021.15,341.34 5068.39,341.34 278.15,1599.71 309.65,1599.71 341.15,1599.71 278.15,3450.11 309.65,3450.11 341.15,3450.11 818.58,3666.46 848.58,3666.46 878.58,3666.46 908.58,3666.46 939.58,3666.35 969.58,3666.35 999.58,3666.35 848.58,3698.64 878.58,3698.64 908.58,3698.64 939.58,3698.53 969.58,3698.53 1639.08,5564.37 3489.48,5564.37 1639.08,5595.86 3489.48,5595.86 1639.08,5627.36 3489.48,5627.36
+VDCIN: C20.1 C21.1 C116.1 C117.1 C127.1 C128.1 C134.1 C135.2 C140.1 C141.1 J18.1 J19.1 J19.2 J19.3 MC3.171 MC3.172 MC3.173 MC3.174 MC3.175 MC3.176 MC3.177 MC3.178 MC3.179 MC3.180 U19.5 U19.6 U19.22 U19.30 U19.31 | length 31.4
  L1-TOP w18: v1(1231.05,4008.6) 1231.05,3987.84 1231.58,3987.31 1234.58,3984.31 v1(1234.58,3978.64)
  other v1: 1510.58,3754.46 1540.58,3754.46 1570.58,3754.46 1510.58,3786.64 1540.58,3786.64 1570.58,3786.64 1476.58,3807.56 1114.66,3827.64 1144.58,3827.64 2401.01,3957.97 2432.5,3957.97 2558.49,3957.97 2638.36,3957.97 2669.86,3957.97 2764.35,3957.97 2795.84,3957.97 2401.01,3989.46 2432.5,3989.46 2526.99,3989.46 2558.49,3989.46 2638.36,3989.46 2669.86,3989.46 2764.35,3989.46 2795.84,3989.46 2401.01,4020.96 2432.5,4020.96 2526.99,4020.96 2558.49,4020.96 2638.36,4020.96 2669.86,4020.96 2764.35,4020.96 2795.84,4020.96 2401.01,4052.46 2432.5,4052.46 2526.99,4052.46 2558.49,4052.46 2638.36,4052.46 2669.86,4052.46 2764.35,4052.46 2795.84,4052.46 684.09,5010 744.09,5010 804.09,5010 684.09,5056 744.09,5056 804.09,5056 648,5186.92
AVDDH_KSZ9031: C82.2 C83.2 C84.2 C85.1 FB2.1 U16.1 U16.12 U16.47 | length 121
  L1-TOP w18: C83.2@4350.06,4914.22 4350.49,4914.64 v1(4350.49,4934.42) ; v1(4412.76,4977.01) 4412.89,4977.14 C82.2@4433.06,4977.14 ; v1(4412.76,5193.55) 4415.35,5196.14 C84.2@4435.06,5196.14 ; v1(4435.86,4894.21) C85.1@4451.61,4894.21 v1(4467.35,4894.21) 4492.21,4894.21 FB2.1@4492.61,4894.61
AVDDL_KSZ9031: C103.1 C104.2 C105.2 FB4.2 U16.4 U16.9 | length 122.8
  L1-TOP w18: v1(4412.76,5036.07) 4433.13,5036.07 C104.2@4434.06,5035.14 ; v1(4412.76,5134.49) 4430.71,5134.49 C105.2@4432.06,5133.14 ; v1(4534.27,5096.15) C103.1@4550.02,5096.15 v1(4565.76,5096.15) 4596.66,5096.15 FB4.2@4610.02,5109.5
AVDDL_PLL_KSZ9031: C96.1 C97.2 FB3.2 U16.44 | length 101.6
  L1-TOP w18: C97.2@4291.06,4914.22 4291.43,4914.59 v1(4291.43,4934.42) ; v1(4415.25,4823.65) C96.1@4431,4823.65 v1(4446.75,4823.65) 4477.65,4823.65 FB3.2@4491,4837
B68_L3N_N5: J10.3 MC3.84 | length 1914.9
  L1-TOP w5.25: MC3.84@2720.08,2883.86 2722.42,2881.52 2756.5,2881.52 2762.78,2887.8 v1@2765.08,2887.8
  L8-SIG2 w3.15: J10.3@1121,2475.78 1155.87,2440.91 1350.18,2440.91 1601.14,2691.86 2404.14,2691.86 2493.27,2781 2551,2781 2570,2800 2570,2838.73 2583.27,2852 2613.27,2852 2639.79,2878.52 2755.8,2878.52 v1@2765.08,2887.8
  other v1: 2765.08,2888.8
B68_L3P_N4: J10.1 MC3.82 | length 1914.9
  L1-TOP w5.25: MC3.82@2720.08,2864.17 2722.42,2866.52 2756.5,2866.52 2762.78,2860.24 v1@2765.08,2860.24
  L8-SIG2 w3.15: J10.1@1121,2397.04 1155.87,2431.91 1353.91,2431.91 1604.86,2682.86 2407.86,2682.86 2497,2772 2554.73,2772 2579,2796.27 2579,2835 2587,2843 2617,2843 2643.52,2869.52 2755.8,2869.52 v1@2765.08,2860.24
  other v1: 2765.08,2859.14
B68_L13N_N1: J10.7 MC3.88 | length 1945.8
  L1-TOP w3.3: MC3.88@2720.08,2923.23 2742.76,2923.23 2748.1,2917.89 2805.8,2917.89 v1@2815.08,2927.17
  L8-SIG2 w3.15: J10.7@1121,2633.26 1155.87,2598.39 1413.39,2598.39 1564,2749 2095,2749 2167,2821 2460.27,2821 2498.27,2859 2546.27,2859 2579.27,2892 2612.27,2892 2638.16,2917.89 2805.8,2917.89 v1@2815.08,2927.17
  other v1: 2815.08,2928.17
B68_L13P_N0: J10.5 MC3.86 | length 1945.8
  L1-TOP w3.3: MC3.86@2720.08,2903.54 2742.67,2903.54 2748.01,2908.89 2805.8,2908.89 v1@2815.08,2899.61
  L8-SIG2 w3.15: J10.5@1121,2554.52 1155.87,2589.39 1417.12,2589.39 1567.73,2740 2098.73,2740 2170.73,2812 2464,2812 2502,2850 2550,2850 2583,2883 2616,2883 2641.89,2908.89 2805.8,2908.89 v1@2815.08,2899.61
  other v1: 2815.08,2898.51
B68_L14N_N3: J10.19 MC3.102 | length 1767.7
  L1-TOP w5.25: MC3.102@2720.08,3061.02 2722.42,3058.68 2756.5,3058.68 2762.78,3064.96 v1@2765.08,3064.96
  L8-SIG2 w3.15: J10.19@1121,3105.7 1155.87,3070.83 1206,3070.83 1221.83,3055 1912,3055 1966,3001 2454.27,3001 2508.27,3055 2565.27,3055 2572.27,3062 2711.68,3062 2718,3055.68 2755.8,3055.68 v1@2765.08,3064.96
  other v1: 2765.08,3065.96
B68_L14P_N2: J10.17 MC3.100 | length 1767.7
  L1-TOP w5.25: MC3.100@2720.08,3041.34 2722.42,3043.68 2756.5,3043.68 2762.78,3037.4 v1@2765.08,3037.4
  L8-SIG2 w3.15: J10.17@1121,3026.96 1155.87,3061.83 1202.27,3061.83 1218.1,3046 1908.27,3046 1962.27,2992 2458,2992 2512,3046 2569,3046 2576,3053 2707.95,3053 2714.27,3046.68 2755.8,3046.68 v1@2765.08,3037.4
  other v1: 2765.08,3036.3
B68_L15N_N5: J10.15 MC3.98 | length 1896.7
  L1-TOP w3.3: MC3.98@2720.08,3021.65 2742.76,3021.65 2748.1,3016.31 2805.8,3016.31 v1@2815.08,3025.59
  L8-SIG2 w3.15: J10.15@1121,2948.22 1155.87,2913.35 1512,2913.35 1554.35,2871 2032.27,2871 2111.27,2950 2366.98,2950 2392.39,2975.4 2476.4,2975.4 2521.36,3020.36 2562.64,3020.36 2565.27,3023 2633.31,3023 2640,3016.31 2805.8,3016.31 v1@2815.08,3025.59
  other v1: 2815.08,3026.59
B68_L15P_N4: J10.13 MC3.96 | length 1896.7
  L1-TOP w3.3: MC3.96@2720.08,3001.97 2742.67,3001.97 2748.01,3007.31 2805.8,3007.31 v1@2815.08,2998.03
  L8-SIG2 w3.15: J10.13@1121,2869.48 1155.87,2904.35 1508.27,2904.35 1550.62,2862 2036,2862 2115,2941 2338,2941 2370.71,2941 2396.12,2966.4 2480.13,2966.4 2480.73,2967 2525.09,3011.36 2566.36,3011.36 2569,3014 2629.58,3014 2636.27,3007.31 2805.8,3007.31 v1@2815.08,2998.03
  other v1: 2815.08,2996.93
B68_L16N_N7: J10.11 MC3.92 | length 1794.4
  L1-TOP w5.25: MC3.92@2720.08,2962.6 2722.42,2960.26 2756.5,2960.26 2762.78,2966.54 v1@2765.08,2966.54
  L8-SIG2 w3.15: J10.11@1121,2790.74 1155.87,2755.87 1490.87,2755.87 1548,2813 2067.27,2813 2153.27,2899 2460.27,2899 2518.53,2957.26 2755.8,2957.26 v1@2765.08,2966.54
  other v1: 2765.08,2967.54
B68_L16P_N6: J10.9 MC3.90 | length 1794.4
  L1-TOP w5.25: MC3.90@2720.08,2942.91 2722.42,2945.26 2756.5,2945.26 2762.78,2938.98 v1@2765.08,2938.98
  L8-SIG2 w3.15: J10.9@1121,2712 1155.87,2746.87 1494.6,2746.87 1551.73,2804 2071,2804 2157,2890 2464,2890 2522.26,2948.26 2755.8,2948.26 v1@2765.08,2938.98
  other v1: 2765.08,2937.88
CLK0A: MC2.10 U2.22 | length 1365.8
  L1-TOP w3.3: v1@4112.18,899.39 4122.44,909.65 4142.18,909.65 4151.82,919.29 4202.17,919.29 4207.51,913.94 U2.22@4219.46,913.94
  L3-SIG1 w3.15: v1(3094.49,1366.09) 3105.74,1354.85 3105.74,1291.54 3487.62,909.65 4101.91,909.65 v1@4112.18,899.39
  other v1: 4112.18,898.39
CLK0B: MC2.12 U2.21 | length 1350.9
  L1-TOP w3.3: v1(4112.18,928.92) 4122.44,918.65 4138.46,918.65 4148.09,928.29 4203.74,928.29 4209.09,933.63 U2.21@4219.46,933.63
  L3-SIG1 w3.15: v1(3125.98,1366.09) 3114.74,1354.85 3114.74,1295.26 3491.35,918.65 4101.91,918.65 v1(4112.18,928.92)
CLK1A: MC2.30 U2.18 | length 1087.3
  L1-TOP w3.3: v1@4217.89,1063.03 4228.16,1052.76 4228.16,1043.57 4252.36,1019.37 4252.36,1016.63 4248.84,1013.11 4248.84,1002.38 U2.18@4247.02,1000.56
  L3-SIG1 w3.15: v1(3389.76,1366.09) 3401.01,1354.85 3401.01,1312.26 3544.27,1169 4148.16,1169 4228.16,1089 4228.16,1073.29 v1@4217.89,1063.03
  other v1: 4216.89,1063.03
CLK1B: MC2.32 U2.17 | length 1087.3
  L1-TOP w3.3: v1(4247.42,1063.03) 4237.16,1052.76 4237.16,1047.3 4261.36,1023.1 4261.36,1016.46 4266.7,1011.12 U2.17@4266.7,1000.56
  L3-SIG1 w3.15: v1(3421.26,1366.09) 3410.01,1354.85 3410.01,1315.99 3548,1178 4151.88,1178 4237.16,1092.73 4237.16,1073.29 v1(4247.42,1063.03)
CLK2A: MC2.66 U2.14 | length 530.1
  L1-TOP w3.3: v1(4118.11,1336.09) 4129.36,1347.34 4129.36,1365.79 4124.02,1371.13 MC2.66@4124.02,1394.09 ; U2.14@4325.76,1000.56 4325.76,1011.12 4331.1,1016.46 4331.1,1023.1 4355.3,1047.3 4355.3,1052.76 v1(4345.04,1063.03)
  L3-SIG1 w3.15: v1(4118.11,1336.09) 4129.36,1324.85 4129.36,1296.27 4249.63,1176 4267.93,1176 4355.3,1088.63 4355.3,1073.29 v1(4345.04,1063.03)
CLK2B: MC2.68 U2.13 | length 530.1
  L1-TOP w3.3: MC2.68@4143.7,1394.09 4143.7,1371.53 4138.36,1366.19 4138.36,1347.34 v1(4149.61,1336.09) ; U2.13@4345.44,1000.56 4343.62,1002.38 4343.62,1013.11 4340.1,1016.63 4340.1,1019.37 4364.3,1043.57 4364.3,1052.76 v1@4374.56,1063.03
  L3-SIG1 w3.15: v1(4149.61,1336.09) 4138.36,1324.85 4138.36,1300 4253.36,1185 4271.66,1185 4364.3,1092.36 4364.3,1073.29 v1@4374.56,1063.03
  other v1: 4375.56,1063.03
CLK3A: MC2.102 U2.10 | length 762.9
  L1-TOP w3.3: U2.10@4373,933.63 4383.37,933.63 4388.71,928.29 4444.37,928.29 4454,918.65 4470.02,918.65 v1(4480.28,928.92)
  L3-SIG1 w3.15: v1(4480.28,928.92) 4490.54,918.65 4535.65,918.65 4857.7,1240.7 4857.7,1354.85 v1(4846.46,1366.09)
CLK3B: MC2.104 U2.9 | length 777.8
  L1-TOP w3.3: U2.9@4373,913.94 4384.94,913.94 4390.29,919.29 4440.64,919.29 4450.27,909.65 4470.02,909.65 v1@4480.28,899.39
  L3-SIG1 w3.15: v1@4480.28,899.39 4490.54,909.65 4539.38,909.65 4866.7,1236.98 4866.7,1354.85 v1(4877.95,1366.09)
  other v1: 4480.28,898.39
